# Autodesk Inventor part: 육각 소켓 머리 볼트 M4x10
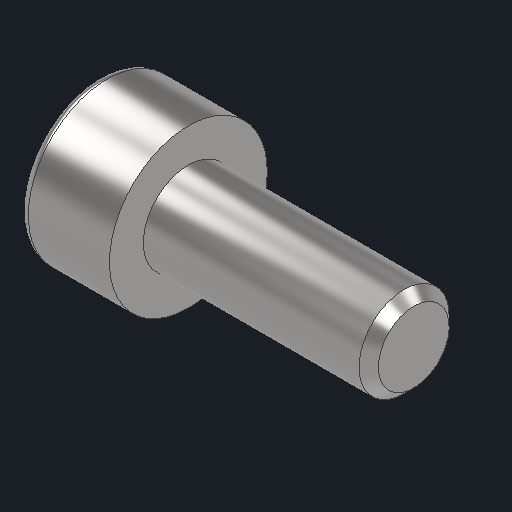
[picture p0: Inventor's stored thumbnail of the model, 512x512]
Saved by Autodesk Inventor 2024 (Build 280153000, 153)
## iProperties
Created: 2024-05
Part Number: 육각 소켓 머리 볼트 M4x10
Material: 강철, 연강
Description: 6각머리 태핑 나사
Document SubType Name: Modeling
Designer: kh_501
Density: 7.85 g/cm^3
Appearance: 기본값
Sending System: Autodesk Inventor 2025
Preprocessor: ST-DEVELOPER v20
Author: jhkim
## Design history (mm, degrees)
node "육각 소켓 머리 볼트 M4x101"
node "솔리드1"
body "Solid1"
